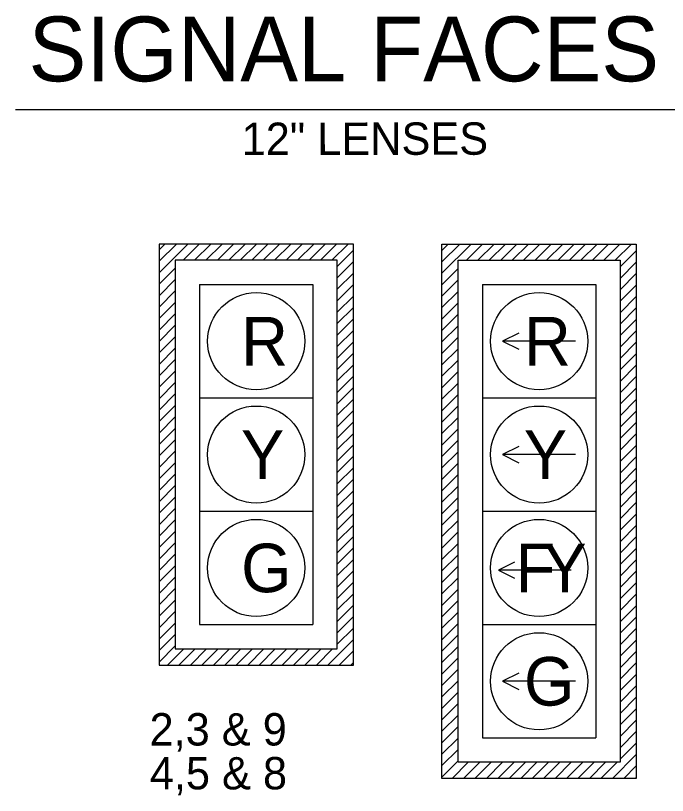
# Model space of a CAD drawing. Extents: x 1280123 to 1281123, y 1892664 to 1893304.
# Drawn here: x 1280308.9 to 1280389.4, y 1892794.6 to 1892890.9 of the extents above; entities that cross this region are included whole.
import ezdxf

# ---------------------------------------------------------------- set-up
doc = ezdxf.new("R2010")
doc.units = 0
doc.layers.add('T_Drafting', color=7, linetype='Continuous')
doc.layers.add('T_Notes', color=7, linetype='Continuous')

msp = doc.modelspace()

# ---------------------------------------------------------------- linework, layer by layer
at = {"layer": 'T_Drafting'}
for p, q in [((1280350.63, 1892862.71), (1280326.63, 1892862.71)), ((1280326.63, 1892862.71), (1280326.63, 1892810.71)), ((1280326.63, 1892859.163), (1280330.177, 1892862.71)), ((1280326.63, 1892860.578), (1280328.763, 1892862.71)), ((1280326.63, 1892861.992), (1280327.348, 1892862.71)), ((1280329.591, 1892860.71), (1280331.591, 1892862.71)), ((1280331.005, 1892860.71), (1280333.005, 1892862.71)), ((1280332.419, 1892860.71), (1280334.419, 1892862.71)), ((1280333.834, 1892860.71), (1280335.834, 1892862.71)), ((1280335.248, 1892860.71), (1280337.248, 1892862.71)), ((1280336.662, 1892860.71), (1280338.662, 1892862.71)), ((1280338.076, 1892860.71), (1280340.076, 1892862.71)), ((1280339.491, 1892860.71), (1280341.491, 1892862.71)), ((1280340.905, 1892860.71), (1280342.905, 1892862.71)), ((1280342.319, 1892860.71), (1280344.319, 1892862.71)), ((1280343.733, 1892860.71), (1280345.733, 1892862.71)), ((1280345.147, 1892860.71), (1280347.147, 1892862.71)), ((1280346.562, 1892860.71), (1280348.562, 1892862.71)), ((1280347.976, 1892860.71), (1280349.976, 1892862.71)), ((1280350.63, 1892810.71), (1280350.63, 1892862.71)), ((1280361.568, 1892796.71), (1280361.568, 1892862.71)), ((1280361.568, 1892862.71), (1280385.568, 1892862.71)), ((1280361.568, 1892859.103), (1280365.175, 1892862.71)), ((1280361.568, 1892860.517), (1280363.761, 1892862.71)), ((1280361.568, 1892861.932), (1280362.347, 1892862.71)), ((1280364.589, 1892860.71), (1280366.589, 1892862.71)), ((1280366.003, 1892860.71), (1280368.003, 1892862.71)), ((1280367.418, 1892860.71), (1280369.418, 1892862.71)), ((1280368.832, 1892860.71), (1280370.832, 1892862.71)), ((1280370.246, 1892860.71), (1280372.246, 1892862.71)), ((1280371.66, 1892860.71), (1280373.66, 1892862.71)), ((1280373.074, 1892860.71), (1280375.074, 1892862.71)), ((1280374.489, 1892860.71), (1280376.489, 1892862.71)), ((1280375.903, 1892860.71), (1280377.903, 1892862.71)), ((1280377.317, 1892860.71), (1280379.317, 1892862.71)), ((1280378.731, 1892860.71), (1280380.731, 1892862.71)), ((1280380.146, 1892860.71), (1280382.146, 1892862.71)), ((1280381.56, 1892860.71), (1280383.56, 1892862.71)), ((1280382.974, 1892860.71), (1280384.974, 1892862.71)), ((1280385.568, 1892862.71), (1280385.568, 1892796.71)), ((1280348.63, 1892859.95), (1280350.63, 1892861.95)), ((1280383.568, 1892859.89), (1280385.568, 1892861.89)), ((1280348.63, 1892858.536), (1280350.63, 1892860.536)), ((1280383.568, 1892858.476), (1280385.568, 1892860.476)), ((1280326.63, 1892857.749), (1280328.63, 1892859.749)), ((1280361.568, 1892857.689), (1280363.568, 1892859.689)), ((1280348.63, 1892857.122), (1280350.63, 1892859.122)), ((1280383.568, 1892857.062), (1280385.568, 1892859.062)), ((1280326.63, 1892856.335), (1280328.63, 1892858.335)), ((1280331.63, 1892857.71), (1280345.63, 1892857.71)), ((1280331.63, 1892857.71), (1280331.63, 1892843.71)), ((1280345.63, 1892857.71), (1280345.63, 1892843.71)), ((1280348.63, 1892855.708), (1280350.63, 1892857.708)), ((1280361.568, 1892856.275), (1280363.568, 1892858.275)), ((1280366.568, 1892857.71), (1280380.568, 1892857.71)), ((1280366.568, 1892857.71), (1280366.568, 1892843.71)), ((1280380.568, 1892857.71), (1280380.568, 1892843.71)), ((1280383.568, 1892855.647), (1280385.568, 1892857.647)), ((1280326.63, 1892854.921), (1280328.63, 1892856.921)), ((1280361.568, 1892854.861), (1280363.568, 1892856.861)), ((1280348.63, 1892854.293), (1280350.63, 1892856.293)), ((1280383.568, 1892854.233), (1280385.568, 1892856.233)), ((1280326.63, 1892853.507), (1280328.63, 1892855.507)), ((1280348.63, 1892852.879), (1280350.63, 1892854.879)), ((1280361.568, 1892853.446), (1280363.568, 1892855.446)), ((1280383.568, 1892852.819), (1280385.568, 1892854.819)), ((1280326.63, 1892852.092), (1280328.63, 1892854.092)), ((1280361.568, 1892852.032), (1280363.568, 1892854.032)), ((1280348.63, 1892851.465), (1280350.63, 1892853.465)), ((1280383.568, 1892851.405), (1280385.568, 1892853.405)), ((1280326.63, 1892850.678), (1280328.63, 1892852.678)), ((1280348.63, 1892850.051), (1280350.63, 1892852.051)), ((1280361.568, 1892850.618), (1280363.568, 1892852.618)), ((1280383.568, 1892849.99), (1280385.568, 1892851.99)), ((1280326.63, 1892849.264), (1280328.63, 1892851.264)), ((1280361.568, 1892849.204), (1280363.568, 1892851.204)), ((1280326.63, 1892847.85), (1280328.63, 1892849.85)), ((1280348.63, 1892848.637), (1280350.63, 1892850.637)), ((1280378.068, 1892850.71), (1280369.068, 1892850.71)), ((1280383.568, 1892848.576), (1280385.568, 1892850.576)), ((1280348.63, 1892847.222), (1280350.63, 1892849.222)), ((1280361.568, 1892847.789), (1280363.568, 1892849.789)), ((1280383.568, 1892847.162), (1280385.568, 1892849.162)), ((1280326.63, 1892846.436), (1280328.63, 1892848.436)), ((1280361.568, 1892846.375), (1280363.568, 1892848.375)), ((1280326.63, 1892845.021), (1280328.63, 1892847.021)), ((1280348.63, 1892845.808), (1280350.63, 1892847.808)), ((1280361.568, 1892844.961), (1280363.568, 1892846.961)), ((1280383.568, 1892845.748), (1280385.568, 1892847.748)), ((1280348.63, 1892844.394), (1280350.63, 1892846.394)), ((1280383.568, 1892844.334), (1280385.568, 1892846.334)), ((1280326.63, 1892843.607), (1280328.63, 1892845.607)), ((1280361.568, 1892843.547), (1280363.568, 1892845.547)), ((1280326.63, 1892842.193), (1280328.63, 1892844.193)), ((1280348.63, 1892842.98), (1280350.63, 1892844.98)), ((1280361.568, 1892842.133), (1280363.568, 1892844.133)), ((1280383.568, 1892842.919), (1280385.568, 1892844.919)), ((1280331.63, 1892843.71), (1280345.63, 1892843.71)), ((1280331.63, 1892843.71), (1280331.63, 1892829.71)), ((1280345.63, 1892843.71), (1280345.63, 1892829.71)), ((1280348.63, 1892841.566), (1280350.63, 1892843.566)), ((1280366.568, 1892843.71), (1280380.568, 1892843.71)), ((1280366.568, 1892843.71), (1280366.568, 1892829.71)), ((1280380.568, 1892843.71), (1280380.568, 1892829.71)), ((1280383.568, 1892841.505), (1280385.568, 1892843.505)), ((1280326.63, 1892840.779), (1280328.63, 1892842.779)), ((1280348.63, 1892840.151), (1280350.63, 1892842.151)), ((1280361.568, 1892840.718), (1280363.568, 1892842.718)), ((1280326.63, 1892839.365), (1280328.63, 1892841.365)), ((1280361.568, 1892839.304), (1280363.568, 1892841.304)), ((1280383.568, 1892840.091), (1280385.568, 1892842.091)), ((1280348.63, 1892838.737), (1280350.63, 1892840.737)), ((1280383.568, 1892838.677), (1280385.568, 1892840.677)), ((1280326.63, 1892837.95), (1280328.63, 1892839.95)), ((1280348.63, 1892837.323), (1280350.63, 1892839.323)), ((1280361.568, 1892837.89), (1280363.568, 1892839.89)), ((1280383.568, 1892837.263), (1280385.568, 1892839.263)), ((1280326.63, 1892836.536), (1280328.63, 1892838.536)), ((1280361.568, 1892836.476), (1280363.568, 1892838.476)), ((1280348.63, 1892835.909), (1280350.63, 1892837.909)), ((1280383.568, 1892835.848), (1280385.568, 1892837.848)), ((1280326.63, 1892835.122), (1280328.63, 1892837.122)), ((1280348.63, 1892834.494), (1280350.63, 1892836.494)), ((1280361.568, 1892835.062), (1280363.568, 1892837.062)), ((1280378.068, 1892836.71), (1280369.068, 1892836.71)), ((1280383.568, 1892834.434), (1280385.568, 1892836.434)), ((1280326.63, 1892833.708), (1280328.63, 1892835.708)), ((1280361.568, 1892833.647), (1280363.568, 1892835.647)), ((1280348.63, 1892833.08), (1280350.63, 1892835.08)), ((1280383.568, 1892833.02), (1280385.568, 1892835.02)), ((1280326.63, 1892832.293), (1280328.63, 1892834.293)), ((1280348.63, 1892831.666), (1280350.63, 1892833.666)), ((1280361.568, 1892832.233), (1280363.568, 1892834.233)), ((1280383.568, 1892831.606), (1280385.568, 1892833.606)), ((1280326.63, 1892830.879), (1280328.63, 1892832.879)), ((1280361.568, 1892830.819), (1280363.568, 1892832.819)), ((1280348.63, 1892830.252), (1280350.63, 1892832.252)), ((1280383.568, 1892830.192), (1280385.568, 1892832.192)), ((1280326.63, 1892829.465), (1280328.63, 1892831.465)), ((1280348.63, 1892828.838), (1280350.63, 1892830.838)), ((1280361.568, 1892829.405), (1280363.568, 1892831.405)), ((1280383.568, 1892828.777), (1280385.568, 1892830.777)), ((1280326.63, 1892828.051), (1280328.63, 1892830.051)), ((1280331.63, 1892829.71), (1280345.63, 1892829.71)), ((1280331.63, 1892829.71), (1280331.63, 1892815.71)), ((1280345.63, 1892829.71), (1280345.63, 1892815.71)), ((1280361.568, 1892827.99), (1280363.568, 1892829.99)), ((1280366.568, 1892829.71), (1280380.568, 1892829.71)), ((1280366.568, 1892829.71), (1280366.568, 1892815.71)), ((1280380.568, 1892829.71), (1280380.568, 1892815.71)), ((1280326.63, 1892826.637), (1280328.63, 1892828.637)), ((1280348.63, 1892827.423), (1280350.63, 1892829.423)), ((1280383.568, 1892827.363), (1280385.568, 1892829.363)), ((1280348.63, 1892826.009), (1280350.63, 1892828.009)), ((1280361.568, 1892826.576), (1280363.568, 1892828.576)), ((1280383.568, 1892825.949), (1280385.568, 1892827.949)), ((1280326.63, 1892825.222), (1280328.63, 1892827.222)), ((1280361.568, 1892825.162), (1280363.568, 1892827.162)), ((1280326.63, 1892823.808), (1280328.63, 1892825.808)), ((1280348.63, 1892824.595), (1280350.63, 1892826.595)), ((1280361.568, 1892823.748), (1280363.568, 1892825.748)), ((1280383.568, 1892824.535), (1280385.568, 1892826.535)), ((1280348.63, 1892823.181), (1280350.63, 1892825.181)), ((1280383.568, 1892823.12), (1280385.568, 1892825.12)), ((1280326.63, 1892822.394), (1280328.63, 1892824.394)), ((1280361.568, 1892822.334), (1280363.568, 1892824.334)), ((1280326.63, 1892820.98), (1280328.63, 1892822.98)), ((1280348.63, 1892821.767), (1280350.63, 1892823.767)), ((1280361.568, 1892820.919), (1280363.568, 1892822.919)), ((1280383.568, 1892821.706), (1280385.568, 1892823.706)), ((1280348.63, 1892820.352), (1280350.63, 1892822.352)), ((1280377.543, 1892822.433), (1280368.543, 1892822.433)), ((1280383.568, 1892820.292), (1280385.568, 1892822.292)), ((1280326.63, 1892819.566), (1280328.63, 1892821.566)), ((1280348.63, 1892818.938), (1280350.63, 1892820.938)), ((1280361.568, 1892819.505), (1280363.568, 1892821.505)), ((1280326.63, 1892818.151), (1280328.63, 1892820.151)), ((1280361.568, 1892818.091), (1280363.568, 1892820.091)), ((1280383.568, 1892818.878), (1280385.568, 1892820.878)), ((1280348.63, 1892817.524), (1280350.63, 1892819.524)), ((1280383.568, 1892817.464), (1280385.568, 1892819.464)), ((1280326.63, 1892816.737), (1280328.63, 1892818.737)), ((1280348.63, 1892816.11), (1280350.63, 1892818.11)), ((1280361.568, 1892816.677), (1280363.568, 1892818.677)), ((1280383.568, 1892816.049), (1280385.568, 1892818.049)), ((1280326.63, 1892815.323), (1280328.63, 1892817.323)), ((1280361.568, 1892815.263), (1280363.568, 1892817.263)), ((1280348.63, 1892814.695), (1280350.63, 1892816.695)), ((1280383.568, 1892814.635), (1280385.568, 1892816.635)), ((1280326.63, 1892813.909), (1280328.63, 1892815.909)), ((1280331.63, 1892815.71), (1280345.63, 1892815.71)), ((1280348.63, 1892813.281), (1280350.63, 1892815.281)), ((1280361.568, 1892813.848), (1280363.568, 1892815.848)), ((1280366.568, 1892815.71), (1280380.568, 1892815.71)), ((1280366.568, 1892815.71), (1280366.568, 1892801.71)), ((1280380.568, 1892815.71), (1280380.568, 1892801.71)), ((1280383.568, 1892813.221), (1280385.568, 1892815.221)), ((1280326.63, 1892812.494), (1280328.63, 1892814.494)), ((1280361.568, 1892812.434), (1280363.568, 1892814.434)), ((1280347.473, 1892810.71), (1280350.63, 1892813.867)), ((1280383.568, 1892811.807), (1280385.568, 1892813.807)), ((1280326.63, 1892811.08), (1280328.63, 1892813.08)), ((1280327.674, 1892810.71), (1280329.674, 1892812.71)), ((1280329.089, 1892810.71), (1280331.089, 1892812.71)), ((1280330.503, 1892810.71), (1280332.503, 1892812.71)), ((1280331.917, 1892810.71), (1280333.917, 1892812.71)), ((1280333.331, 1892810.71), (1280335.331, 1892812.71)), ((1280334.745, 1892810.71), (1280336.745, 1892812.71)), ((1280336.16, 1892810.71), (1280338.16, 1892812.71)), ((1280337.574, 1892810.71), (1280339.574, 1892812.71)), ((1280338.988, 1892810.71), (1280340.988, 1892812.71)), ((1280340.402, 1892810.71), (1280342.402, 1892812.71)), ((1280341.816, 1892810.71), (1280343.816, 1892812.71)), ((1280343.231, 1892810.71), (1280345.231, 1892812.71)), ((1280344.645, 1892810.71), (1280346.645, 1892812.71)), ((1280346.059, 1892810.71), (1280348.059, 1892812.71)), ((1280348.888, 1892810.71), (1280350.63, 1892812.453)), ((1280361.568, 1892811.02), (1280363.568, 1892813.02)), ((1280383.568, 1892810.393), (1280385.568, 1892812.393)), ((1280361.568, 1892809.606), (1280363.568, 1892811.606)), ((1280326.63, 1892810.71), (1280350.63, 1892810.71)), ((1280350.302, 1892810.71), (1280350.63, 1892811.039)), ((1280383.568, 1892808.978), (1280385.568, 1892810.978)), ((1280361.568, 1892808.192), (1280363.568, 1892810.192)), ((1280383.568, 1892807.564), (1280385.568, 1892809.564)), ((1280361.568, 1892806.777), (1280363.568, 1892808.777)), ((1280378.068, 1892808.71), (1280369.068, 1892808.71)), ((1280383.568, 1892806.15), (1280385.568, 1892808.15)), ((1280361.568, 1892805.363), (1280363.568, 1892807.363)), ((1280383.568, 1892804.736), (1280385.568, 1892806.736)), ((1280361.568, 1892803.949), (1280363.568, 1892805.949)), ((1280361.568, 1892802.535), (1280363.568, 1892804.535)), ((1280383.568, 1892803.321), (1280385.568, 1892805.321)), ((1280383.568, 1892801.907), (1280385.568, 1892803.907)), ((1280361.568, 1892801.12), (1280363.568, 1892803.12)), ((1280361.568, 1892799.706), (1280363.568, 1892801.706)), ((1280366.568, 1892801.71), (1280380.568, 1892801.71)), ((1280383.568, 1892800.493), (1280385.568, 1892802.493)), ((1280383.568, 1892799.079), (1280385.568, 1892801.079)), ((1280361.568, 1892798.292), (1280363.568, 1892800.292)), ((1280361.568, 1892796.878), (1280363.568, 1892798.878)), ((1280382.614, 1892796.71), (1280385.568, 1892799.665)), ((1280362.815, 1892796.71), (1280364.815, 1892798.71)), ((1280364.229, 1892796.71), (1280366.229, 1892798.71)), ((1280365.643, 1892796.71), (1280367.643, 1892798.71)), ((1280367.057, 1892796.71), (1280369.057, 1892798.71)), ((1280368.471, 1892796.71), (1280370.471, 1892798.71)), ((1280369.886, 1892796.71), (1280371.886, 1892798.71)), ((1280371.3, 1892796.71), (1280373.3, 1892798.71)), ((1280372.714, 1892796.71), (1280374.714, 1892798.71)), ((1280374.128, 1892796.71), (1280376.128, 1892798.71)), ((1280375.543, 1892796.71), (1280377.543, 1892798.71)), ((1280376.957, 1892796.71), (1280378.957, 1892798.71)), ((1280378.371, 1892796.71), (1280380.371, 1892798.71)), ((1280379.785, 1892796.71), (1280381.785, 1892798.71)), ((1280381.199, 1892796.71), (1280383.199, 1892798.71)), ((1280384.028, 1892796.71), (1280385.568, 1892798.25)), ((1280385.442, 1892796.71), (1280385.568, 1892796.836)), ((1280385.568, 1892796.71), (1280361.568, 1892796.71))]:
    msp.add_line(p, q, dxfattribs=at)
for points in [[(1280348.63, 1892812.71), (1280348.63, 1892860.71), (1280328.63, 1892860.71), (1280328.63, 1892812.71)], [(1280363.568, 1892798.71), (1280363.568, 1892860.71), (1280383.568, 1892860.71), (1280383.568, 1892798.71)]]:
    msp.add_lwpolyline(points, close=True, dxfattribs=at)
for points in [[(1280371.068, 1892851.71), (1280369.068, 1892850.71), (1280371.068, 1892849.71)], [(1280371.068, 1892837.71), (1280369.068, 1892836.71), (1280371.068, 1892835.71)], [(1280370.543, 1892823.433), (1280368.543, 1892822.433), (1280370.543, 1892821.433)], [(1280371.068, 1892809.71), (1280369.068, 1892808.71), (1280371.068, 1892807.71)]]:
    msp.add_lwpolyline(points, dxfattribs=at)
for centre in [(1280338.63, 1892850.71), (1280373.568, 1892850.71), (1280338.63, 1892836.71), (1280373.568, 1892836.71), (1280338.63, 1892822.71), (1280373.568, 1892822.71), (1280373.568, 1892808.71)]:
    msp.add_circle(centre, 6, dxfattribs=at)
at = {"layer": 'T_Notes'}
msp.add_line((1280308.906, 1892879.338), (1280407.091, 1892879.338), dxfattribs=at)

# ---------------------------------------------------------------- texts
at = {"layer": 'T_Drafting'}
msp.add_text('12" LENSES', height=4, rotation=0.07203, dxfattribs=at).set_placement((1280336.832, 1892873.704))
for s, p in [('R', (1280336.765, 1892847.711)), ('R', (1280371.703, 1892847.711)), ('Y', (1280336.741, 1892833.711)), ('Y', (1280371.679, 1892833.711)), ('G', (1280336.764, 1892819.711)), ('F', (1280370.663, 1892819.711)), ('Y', (1280374.087, 1892819.711)), ('G', (1280371.702, 1892805.711))]:
    msp.add_text(s, height=5.998, dxfattribs=at).set_placement(p)
at = {"layer": 'T_Notes'}
for s, height, p in [('SIGNAL FACES', 8, (1280310.505, 1892882.807)), ('2,3 & 9', 4, (1280325.455, 1892800.78)), ('4,5 & 8', 4, (1280325.483, 1892795.362))]:
    msp.add_text(s, height=height, dxfattribs=at).set_placement(p)

doc.saveas('drawing.dxf')
